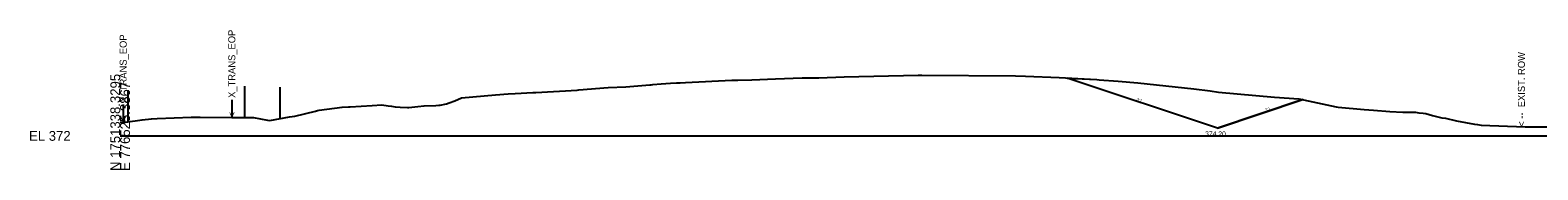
# Model space of a CAD drawing. Extents: x 776426 to 854588, y 1736205 to 1756790.
# Drawn here: x 805845.1 to 806275.5, y 1741205.1 to 1741244.9 of the extents above; entities that cross this region are included whole.
import ezdxf

# ---------------------------------------------------------------- set-up
doc = ezdxf.new("R2010")
doc.units = 0
for name, color, linetype in [('DTM CONTOURS_MAJOR_TX', 7, 'Continuous'), ('DTM_X_FLOW_ARROWS', 7, 'Continuous'), ('TRANS_EOP_PAVED', 7, 'Continuous'), ('TRANS_UNPAVED_SHOULDERS', 7, 'Continuous'), ('X_TRANS_EOP', 7, 'Continuous'), ('XS_M_SHAPES_EARTHWORK', 7, 'Continuous'), ('XS_P_FINISHED_GRADE', 7, 'Continuous'), ('XS_P_TX_DCH', 7, 'Continuous'), ('XS_P_TX_FS_BS', 7, 'Continuous'), ('XS_X_PAVEMENT', 7, 'Continuous'), ('XS_X_ROW', 7, 'Continuous')]:
    doc.layers.add(name, color=color, linetype=linetype)

msp = doc.modelspace()

# ---------------------------------------------------------------- linework, layer by layer
at = {"layer": 'DTM CONTOURS_MAJOR_TX'}
msp.add_line((805870.79, 1741214.76), (806370.79, 1741214.76), dxfattribs=at)
at = {"layer": 'DTM_X_FLOW_ARROWS'}
msp.add_lwpolyline([(805870.79, 1741218.65), (805871.66, 1741218.67), (805872.34, 1741218.69), (805877.07, 1741219.31), (805879.74, 1741219.65), (805881.4, 1741219.71), (805891.06, 1741220.1), (805892.3, 1741220.09), (805893.61, 1741220.08), (805902.67, 1741220.02), (805905.14, 1741220), (805908.27, 1741219.98), (805908.85, 1741220.05), (805912.81, 1741219.22), (805913.48, 1741219.13), (805919.17, 1741220.17), (805920.62, 1741220.43), (805926.52, 1741221.83), (805927.13, 1741221.99), (805927.63, 1741222.08), (805934.2, 1741222.97), (805936.02, 1741223.05), (805936.47, 1741223.05), (805942.74, 1741223.44), (805945.51, 1741223.62), (805947.28, 1741223.37), (805948.22, 1741223.21), (805949.26, 1741223.02), (805950.72, 1741222.98), (805952.82, 1741222.87), (805953.24, 1741222.84), (805955.78, 1741223.11), (805957.55, 1741223.35), (805960.95, 1741223.45), (805961.75, 1741223.52), (805962.14, 1741223.53), (805963.96, 1741223.92), (805964.67, 1741224.15), (805966.35, 1741224.75), (805968.22, 1741225.6), (805977.98, 1741226.49), (805981.55, 1741226.72), (805983.59, 1741226.86), (805988.6, 1741227.12), (805989.41, 1741227.16), (806001.24, 1741227.84), (806001.68, 1741227.88), (806010.13, 1741228.52), (806015.18, 1741228.74), (806021.96, 1741229.34), (806022.36, 1741229.37), (806022.81, 1741229.41), (806025.23, 1741229.65), (806027.89, 1741229.81), (806029.63, 1741229.9), (806030.63, 1741229.94), (806032.14, 1741230), (806034.12, 1741230.08), (806043.54, 1741230.57), (806045.43, 1741230.67), (806047.11, 1741230.69), (806051.09, 1741230.73), (806057.83, 1741231.01), (806065.45, 1741231.3), (806070.28, 1741231.29), (806077.49, 1741231.57), (806098.6, 1741232.11), (806099.68, 1741232.11), (806126.37, 1741231.92), (806129.23, 1741231.77), (806138.8, 1741231.39), (806149.62, 1741230.8), (806150.25, 1741230.75), (806155.71, 1741230.33), (806161.26, 1741229.91), (806177.29, 1741228.18), (806181.92, 1741227.64), (806184.34, 1741227.23), (806200.28, 1741225.81), (806207.28, 1741225.36), (806217.9, 1741223.04), (806218.5, 1741222.92), (806225.87, 1741222.3), (806228.62, 1741222.1), (806233.23, 1741221.76), (806236.94, 1741221.5), (806237.5, 1741221.49), (806238.23, 1741221.51), (806240.6, 1741221.5), (806241.53, 1741221.32), (806242.76, 1741221.22), (806243.5, 1741221.11), (806245.39, 1741220.56), (806248.12, 1741219.9), (806249.11, 1741219.83), (806252.25, 1741219.02), (806257.38, 1741218.09), (806258.26, 1741217.96), (806259.35, 1741217.84), (806271.89, 1741217.31), (806272.23, 1741217.31), (806282.02, 1741217.3)], dxfattribs=at)
at = {"layer": 'TRANS_EOP_PAVED'}
for p, q in [((805906.25, 1741228.99), (805906.25, 1741219.99)), ((805906.25, 1741228.99), (805906.25, 1741219.99)), ((805873, 1741227.78), (805873, 1741218.78)), ((805873, 1741227.78), (805873, 1741218.78))]:
    msp.add_line(p, q, dxfattribs=at)
at = {"layer": 'TRANS_UNPAVED_SHOULDERS'}
msp.add_line((805916.35, 1741228.65), (805916.35, 1741219.65), dxfattribs=at)
msp.add_line((805916.35, 1741228.65), (805916.35, 1741219.65), dxfattribs=at)
at = {"layer": 'X_TRANS_EOP'}
for p, q in [((805902.66, 1741225.02), (805902.66, 1741220.02)), ((805902.66, 1741225.02), (805902.66, 1741220.02)), ((805871.65, 1741223.67), (805871.65, 1741218.67)), ((805871.65, 1741223.67), (805871.65, 1741218.67))]:
    msp.add_line(p, q, dxfattribs=at)
at = {"layer": 'XS_M_SHAPES_EARTHWORK'}
msp.add_lwpolyline([(806177.29, 1741228.18), (806181.92, 1741227.64), (806184.34, 1741227.23), (806200.28, 1741225.81), (806207.28, 1741225.36), (806208.44, 1741225.11), (806184, 1741216.96), (806141.09, 1741231.26), (806149.62, 1741230.8), (806150.25, 1741230.75), (806155.71, 1741230.33), (806161.26, 1741229.91)], close=True, dxfattribs=at)
at = {"layer": 'XS_P_FINISHED_GRADE'}
for q in [(806141.09, 1741231.26), (806208.44, 1741225.11)]:
    msp.add_line((806184, 1741216.96), q, dxfattribs=at)

# ---------------------------------------------------------------- texts
at = {"layer": 'DTM CONTOURS_MAJOR_TX'}
for s, p in [('N 1751338.3295', (805870.79, 1741204.76)), ('E 776525.3867', (805873.59, 1741204.76))]:
    msp.add_text(s, height=2.8, rotation=90, dxfattribs=at).set_placement(p)
msp.add_text('EL 372', height=2.8, dxfattribs=at).set_placement((805844.79, 1741213.36))
at = {"layer": 'XS_P_TX_DCH'}
msp.add_text('374.20', height=1.4, dxfattribs=at).set_placement((806180.51, 1741214.63))
at = {"layer": 'XS_P_TX_FS_BS'}
for rotation, p in [(341.5651, (806160.9, 1741224.88)), (18.4349, (806197.75, 1741221.76))]:
    msp.add_text('3:1', height=0.8, rotation=rotation, dxfattribs=at).set_placement(p)
at = {"layer": 'XS_X_PAVEMENT'}
for p in [(805872.65, 1741218.67), (805903.66, 1741220.02)]:
    msp.add_text('< --  X_TRANS_EOP', height=2, rotation=90, dxfattribs=at).set_placement(p)
at = {"layer": 'XS_X_ROW'}
msp.add_text('< --  EXIST. ROW', height=2, rotation=90, dxfattribs=at).set_placement((806271.79, 1741217.36))

doc.saveas('drawing.dxf')
